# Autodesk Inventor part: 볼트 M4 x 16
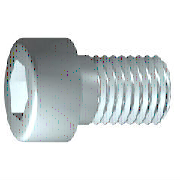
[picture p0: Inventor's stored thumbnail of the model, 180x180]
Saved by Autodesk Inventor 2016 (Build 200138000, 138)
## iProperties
IsCustomPart: 1
Created: 2012-02
Part Number: 볼트 M4 x 16
Material: 스테인리스강
Description: 6각 소켓 머리 캡 나사
Document SubType Name: Modeling
Standard: ISO 4762
Designer: mduedu
Standard Revision: Fourth edition 2004-03-01
Standards Organization: ISO
Language: ko-KR
Size Designation: M4 x 16
Categories: <MemberInstance><Categories><Category DisplayName="조임쇠" InternalName="e4da775c-781d-43d5-af7c-5136215cf5a6" Mnemonic="FSTN"><Category DisplayName="볼트" InternalN
Density: 8.08 g/cm^3
Appearance: 반광택
Mass: 2.70334 g
Surface Area: 3.81118 cm^2
Volume: 0.334572 cm^3
Author: mduedu
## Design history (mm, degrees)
sketch "스케치1"
  geometry: L1 (-1, 0)-(16, 0); L2 (16, 0)-(16, 2); L3 (16, 2)-(1.75, 2); L4 (1.75, 2)-(1.32, 2); L5 (1.32, 2)-(0, 2); L6 (0, 2)-(0, 3.5); L7 (0, 3.5)-(-4, 3.5); L8 (-4, 3.5)-(-4, 1.732); L9 (-4, 1.732)-(-2, 1.732); L10 (-2, 1.732)-(-1, 0); L11 (-8, 0)-(20, 0) reference; L12 (0, -0.7)-(0, 4.2) reference; L13 (1.75, 2)-(0, 2)
  constraints: 22 end point, 6 parallel, 2 collinear, 2 perpendicular, 1 horizontal, 1 point on line
  dimensions: "d1" = 14.25 distance from line of L3.end L2 (= GEL); "d2" = 0.42952 distance of L4.end L3.end (computed from GAL); "d3" = 4 distance between parallel lines of L8 L6 (= KOH); "d4" = 2 distance of L8.end L9.end (= INTI); "d5" = 60 deg angle of L10 L1; "d6" = 4 diameter of L3 L1 (= GD); "d7" = 4 diameter of L5 L1 (= BDM); "d8" = 3.4641 diameter of L9 L1 (= 1.1547 x SW); "d9" = 7 diameter of L7 L1 (= KOD); "d26" = 16 distance between parallel lines of L12 L2 (= NLG)
revolve "본체" sketch "스케치1" stored, may be unused: angle "d10" = 90 deg
sketch "스케치2"
  geometry: L1 (0, -4.9)-(0, 4.9) reference; L2 (-4.9, 0)-(4.9, 0) reference; L3 (1.732, 0)-(0.866, -1.5); L4 (0.866, -1.5)-(-0.866, -1.5); L5 (-0.866, -1.5)-(-1.732, 0); L6 (-1.732, 0)-(-0.866, 1.5); L7 (-0.866, 1.5)-(0.866, 1.5); L8 (0.866, 1.5)-(1.732, 0); 2 further points
  constraints: 12 end point, 1 coincident, 1 horizontal alignment, 1 point on line, 12 other
extrude "슬롯" join sketch "스케치2" stored distance "d11" = 10; taper "d12" = 0 deg
workplane "Work Plane1"
fillet "Fillet2" dims "d30" = 0.1 (= R)
body "Solid1"
fillet "모깎기1" dims "d17" = 0.4 (= RR)
feature "스레드" dims "d13" = 14.25 (= GEL), "d14" = 0
chamfer "모따기1" distance "d15" = 0.42941 (= -0.5 x SPD + 0.5 x GD); stored, may be unused: second distance "d16" = 0.42941 (= GUL), angle "d27" = 45 deg
other parameters: "GD" = 4 [user parameter; used in 2 equation terms], "NLG" = 16 [user parameter; used in 1 equation term], "GEL" = 14.25 [user parameter; used in 2 equation terms], "KOD" = 7 [user parameter; used in 1 equation term], "KOH" = 4 [user parameter; used in 1 equation term], "INTI" = 2 [user parameter; used in 1 equation term], "GAL" = 0.42941 (= 0.61345 x PTC) [user parameter; used in 1 equation term], "GUL" = 0.42941 (= 0.61345 x PTC) [user parameter; used in 1 equation term], "BDM" = 4 (= NND) [user parameter; used in 1 equation term], "SW" = 3 [user parameter; used in 2 equation terms], "RR" = 0.4 [user parameter; used in 1 equation term], "SPD" = 3.14117 (= NND - 1.2269 x PTC) [user parameter; used in 1 equation term], "d19" = 0, "d28" = 0, "d29" = 0, "R" = 0.1 [user parameter; used in 1 equation term], "TOA" = 30 deg [user parameter], "GD1" = 3.14117 (= THREADDIA - 1.2269 x PTC) [user parameter], "THREADDIA" = 4 [user parameter; used in 1 equation term], "FAWI" = 45 deg [user parameter], "TPU" = 14.28571 (computed from PTC) [user parameter], "PTC" = 0.7 [user parameter; used in 5 equation terms], "NND" = 4 [user parameter; used in 2 equation terms], "E0" = 3.465 (= 1.155 x SW) [user parameter]
